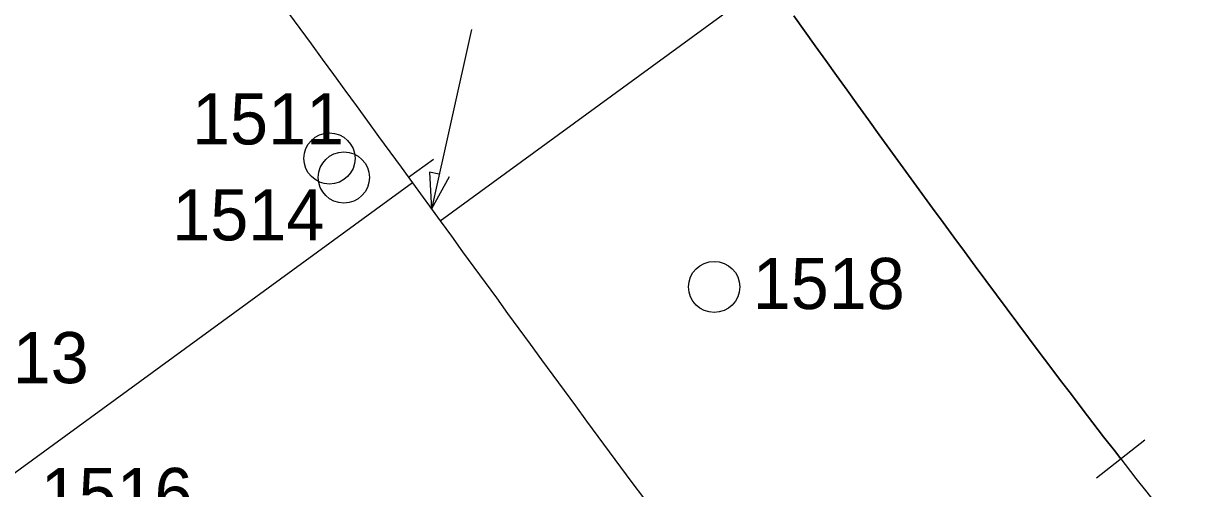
# Model space of a CAD drawing. Extents: x 7581380 to 7602708, y 543740 to 556109.
# Drawn here: x 7591832.4 to 7591946.3, y 549891.7 to 549937.2 of the extents above; entities that cross this region are included whole.
import ezdxf

# ---------------------------------------------------------------- set-up
doc = ezdxf.new("R2010")
doc.units = 0
for name, color, linetype in [('E_SURV_BNDRY_AccessControl', 7, 'Continuous'), ('E_SURV_BNDRY_ROW', 7, 'Continuous'), ('E_SURV_MON_FdMon', 7, 'Continuous'), ('E_SURV_MON_FdMonTx', 7, 'Continuous'), ('P_RW_ALIGN_Prim', 7, 'Continuous'), ('P_RW_ALIGN_PrimTic', 7, 'Continuous'), ('P_RW_ALIGN_PrimTx', 7, 'Continuous'), ('P_RW_FILE_AreaShapeFee', 7, 'Continuous'), ('P_RW_FILE_AreaShapeRemain', 7, 'Continuous')]:
    doc.layers.add(name, color=color, linetype=linetype)

msp = doc.modelspace()

# ---------------------------------------------------------------- linework, layer by layer
at = {"layer": 'E_SURV_BNDRY_AccessControl'}
msp.add_line((7591937.46, 549892.81), (7591942.19, 549896.5), dxfattribs=at)
msp.add_lwpolyline([(7591907.82, 549937.96), (7591908.87, 549936.5), (7591909.92, 549935.04), (7591910.96, 549933.58), (7591912.01, 549932.13), (7591913.05, 549930.68), (7591914.1, 549929.23), (7591915.14, 549927.78), (7591916.18, 549926.34), (7591917.23, 549924.9), (7591918.27, 549923.46), (7591919.31, 549922.03), (7591920.35, 549920.6), (7591921.4, 549919.17), (7591922.44, 549917.75), (7591923.48, 549916.33), (7591924.53, 549914.91), (7591925.57, 549913.5), (7591926.61, 549912.09), (7591927.66, 549910.68), (7591928.7, 549909.28), (7591929.75, 549907.88), (7591930.79, 549906.48), (7591931.84, 549905.09), (7591932.89, 549903.7), (7591933.94, 549902.32), (7591934.99, 549900.94), (7591936.04, 549899.56), (7591937.09, 549898.19), (7591938.14, 549896.82), (7591939.2, 549895.46), (7591939.82, 549894.65)], dxfattribs=at)
at = {"layer": 'E_SURV_BNDRY_ROW'}
msp.add_lwpolyline([(7591939.82, 549894.65), (7591940.25, 549894.1), (7591941.31, 549892.75), (7591942.37, 549891.4), (7591943.43, 549890.05), (7591944.49, 549888.71), (7591945.56, 549887.37), (7591946.62, 549886.04)], dxfattribs=at)
at = {"layer": 'E_SURV_MON_FdMon'}
for centre in [(7591862.4, 549924.02), (7591863.81, 549922.16), (7591900.04, 549911.46)]:
    msp.add_circle(centre, 2.5, dxfattribs=at)
at = {"layer": 'P_RW_ALIGN_Prim'}
msp.add_line((7591870.51, 549921.65), (7591873.23, 549917.92), dxfattribs=at)
msp.add_line((7591870.51, 549921.65), (7591873.23, 549917.92), dxfattribs=at)
for points in [[(7591858.39, 549938.23), (7591859.49, 549936.72), (7591860.6, 549935.22), (7591861.7, 549933.71), (7591862.8, 549932.21), (7591863.9, 549930.7), (7591865.01, 549929.19), (7591866.11, 549927.68), (7591867.21, 549926.18), (7591868.31, 549924.67), (7591869.41, 549923.16), (7591870.51, 549921.65)], [(7591873.23, 549917.92), (7591874.33, 549916.41), (7591875.43, 549914.9), (7591876.53, 549913.39), (7591877.63, 549911.88), (7591878.73, 549910.38), (7591879.83, 549908.87), (7591880.94, 549907.36), (7591882.04, 549905.85), (7591883.14, 549904.35), (7591884.25, 549902.84), (7591885.35, 549901.34), (7591886.46, 549899.84), (7591887.56, 549898.33), (7591888.67, 549896.83), (7591889.78, 549895.33), (7591890.89, 549893.83), (7591892, 549892.33), (7591893.12, 549890.83)]]:
    msp.add_lwpolyline(points, dxfattribs=at)
at = {"layer": 'P_RW_ALIGN_PrimTic'}
for points in [[(7591873.23, 549917.92), (7591994.43, 550006.3)], [(7591872.57, 549923.92), (7591870.14, 549922.15)], [(7591870.51, 549921.65), (7591749.31, 549833.27)]]:
    msp.add_lwpolyline(points, dxfattribs=at)
at = {"layer": 'P_RW_ALIGN_PrimTx'}
for p, q in [((7591876.31, 549936.63), (7591872.4, 549919.06)), ((7591873.15, 549922.48), (7591872.18, 549922.69)), ((7591872.18, 549922.69), (7591872.4, 549919.06)), ((7591872.4, 549919.06), (7591874.13, 549922.26))]:
    msp.add_line(p, q, dxfattribs=at)
at = {"layer": 'P_RW_FILE_AreaShapeFee'}
for points in [[(7591907.82, 549937.96), (7591908.87, 549936.5), (7591909.92, 549935.04), (7591910.96, 549933.58), (7591912.01, 549932.13), (7591913.05, 549930.68), (7591914.1, 549929.23), (7591915.14, 549927.78), (7591916.18, 549926.34), (7591917.23, 549924.9), (7591918.27, 549923.46), (7591919.31, 549922.03), (7591920.35, 549920.6), (7591921.4, 549919.17), (7591922.44, 549917.75), (7591923.48, 549916.33), (7591924.53, 549914.91), (7591925.57, 549913.5), (7591926.61, 549912.09), (7591927.66, 549910.68), (7591928.7, 549909.28), (7591929.75, 549907.88), (7591930.79, 549906.48), (7591931.84, 549905.09), (7591932.89, 549903.7), (7591933.94, 549902.32), (7591934.99, 549900.94), (7591936.04, 549899.56), (7591937.09, 549898.19), (7591938.14, 549896.82), (7591939.2, 549895.46), (7591939.82, 549894.65)], [(7591939.82, 549894.65), (7591939.2, 549895.46), (7591938.14, 549896.82), (7591937.09, 549898.19), (7591936.04, 549899.56), (7591934.99, 549900.94), (7591933.94, 549902.32), (7591932.89, 549903.7), (7591931.84, 549905.09), (7591930.79, 549906.48), (7591929.75, 549907.88), (7591928.7, 549909.28), (7591927.66, 549910.68), (7591926.61, 549912.09), (7591925.57, 549913.5), (7591924.53, 549914.91), (7591923.48, 549916.33), (7591922.44, 549917.75), (7591921.4, 549919.17), (7591920.35, 549920.6), (7591919.31, 549922.03), (7591918.27, 549923.46), (7591917.23, 549924.9), (7591916.18, 549926.34), (7591915.14, 549927.78), (7591914.1, 549929.23), (7591913.05, 549930.68), (7591912.01, 549932.13), (7591910.96, 549933.58), (7591909.92, 549935.04), (7591908.87, 549936.5), (7591907.82, 549937.96)], [(7591907.82, 549937.96), (7591908.87, 549936.5), (7591909.92, 549935.04), (7591910.96, 549933.58), (7591912.01, 549932.13), (7591913.05, 549930.68), (7591914.1, 549929.23), (7591915.14, 549927.78), (7591916.18, 549926.34), (7591917.23, 549924.9), (7591918.27, 549923.46), (7591919.31, 549922.03), (7591920.35, 549920.6), (7591921.4, 549919.17), (7591922.44, 549917.75), (7591923.48, 549916.33), (7591924.53, 549914.91), (7591925.57, 549913.5), (7591926.61, 549912.09), (7591927.66, 549910.68), (7591928.7, 549909.28), (7591929.75, 549907.88), (7591930.79, 549906.48), (7591931.84, 549905.09), (7591932.89, 549903.7), (7591933.94, 549902.32), (7591934.99, 549900.94), (7591936.04, 549899.56), (7591937.09, 549898.19), (7591938.14, 549896.82), (7591939.2, 549895.46), (7591939.82, 549894.65)], [(7591907.82, 549937.96), (7591908.87, 549936.5), (7591909.92, 549935.04), (7591910.96, 549933.58), (7591912.01, 549932.13), (7591913.05, 549930.68), (7591914.1, 549929.23), (7591915.14, 549927.78), (7591916.18, 549926.34), (7591917.23, 549924.9), (7591918.27, 549923.46), (7591919.31, 549922.03), (7591920.35, 549920.6), (7591921.4, 549919.17), (7591922.44, 549917.75), (7591923.48, 549916.33), (7591924.53, 549914.91), (7591925.57, 549913.5), (7591926.61, 549912.09), (7591927.66, 549910.68), (7591928.7, 549909.28), (7591929.75, 549907.88), (7591930.79, 549906.48), (7591931.84, 549905.09), (7591932.89, 549903.7), (7591933.94, 549902.32), (7591934.99, 549900.94), (7591936.04, 549899.56), (7591937.09, 549898.19), (7591938.14, 549896.82), (7591939.2, 549895.46), (7591939.82, 549894.65)], [(7591907.82, 549937.96), (7591908.87, 549936.5), (7591909.92, 549935.04), (7591910.96, 549933.58), (7591912.01, 549932.13), (7591913.05, 549930.68), (7591914.1, 549929.23), (7591915.14, 549927.78), (7591916.18, 549926.34), (7591917.23, 549924.9), (7591918.27, 549923.46), (7591919.31, 549922.03), (7591920.35, 549920.6), (7591921.4, 549919.17), (7591922.44, 549917.75), (7591923.48, 549916.33), (7591924.53, 549914.91), (7591925.57, 549913.5), (7591926.61, 549912.09), (7591927.66, 549910.68), (7591928.7, 549909.28), (7591929.75, 549907.88), (7591930.79, 549906.48), (7591931.84, 549905.09), (7591932.89, 549903.7), (7591933.94, 549902.32), (7591934.99, 549900.94), (7591936.04, 549899.56), (7591937.09, 549898.19), (7591938.14, 549896.82), (7591939.2, 549895.46), (7591939.82, 549894.65)], [(7591939.82, 549894.65), (7591939.2, 549895.46), (7591938.14, 549896.82), (7591937.09, 549898.19), (7591936.04, 549899.56), (7591934.99, 549900.94), (7591933.94, 549902.32), (7591932.89, 549903.7), (7591931.84, 549905.09), (7591930.79, 549906.48), (7591929.75, 549907.88), (7591928.7, 549909.28), (7591927.66, 549910.68), (7591926.61, 549912.09), (7591925.57, 549913.5), (7591924.53, 549914.91), (7591923.48, 549916.33), (7591922.44, 549917.75), (7591921.4, 549919.17), (7591920.35, 549920.6), (7591919.31, 549922.03), (7591918.27, 549923.46), (7591917.23, 549924.9), (7591916.18, 549926.34), (7591915.14, 549927.78), (7591914.1, 549929.23), (7591913.05, 549930.68), (7591912.01, 549932.13), (7591910.96, 549933.58), (7591909.92, 549935.04), (7591908.87, 549936.5), (7591907.82, 549937.96)], [(7591907.82, 549937.96), (7591908.87, 549936.5), (7591909.92, 549935.04), (7591910.96, 549933.58), (7591912.01, 549932.13), (7591913.05, 549930.68), (7591914.1, 549929.23), (7591915.14, 549927.78), (7591916.18, 549926.34), (7591917.23, 549924.9), (7591918.27, 549923.46), (7591919.31, 549922.03), (7591920.35, 549920.6), (7591921.4, 549919.17), (7591922.44, 549917.75), (7591923.48, 549916.33), (7591924.53, 549914.91), (7591925.57, 549913.5), (7591926.61, 549912.09), (7591927.66, 549910.68), (7591928.7, 549909.28), (7591929.75, 549907.88), (7591930.79, 549906.48), (7591931.84, 549905.09), (7591932.89, 549903.7), (7591933.94, 549902.32), (7591934.99, 549900.94), (7591936.04, 549899.56), (7591937.09, 549898.19), (7591938.14, 549896.82), (7591939.2, 549895.46), (7591939.82, 549894.65)], [(7591907.82, 549937.96), (7591908.87, 549936.5), (7591909.92, 549935.04), (7591910.96, 549933.58), (7591912.01, 549932.13), (7591913.05, 549930.68), (7591914.1, 549929.23), (7591915.14, 549927.78), (7591916.18, 549926.34), (7591917.23, 549924.9), (7591918.27, 549923.46), (7591919.31, 549922.03), (7591920.35, 549920.6), (7591921.4, 549919.17), (7591922.44, 549917.75), (7591923.48, 549916.33), (7591924.53, 549914.91), (7591925.57, 549913.5), (7591926.61, 549912.09), (7591927.66, 549910.68), (7591928.7, 549909.28), (7591929.75, 549907.88), (7591930.79, 549906.48), (7591931.84, 549905.09), (7591932.89, 549903.7), (7591933.94, 549902.32), (7591934.99, 549900.94), (7591936.04, 549899.56), (7591937.09, 549898.19), (7591938.14, 549896.82), (7591939.2, 549895.46), (7591939.82, 549894.65)]]:
    msp.add_lwpolyline(points, dxfattribs=at)
at = {"layer": 'P_RW_FILE_AreaShapeRemain'}
for points in [[(7591907.82, 549937.96), (7591908.87, 549936.5), (7591909.92, 549935.04), (7591910.96, 549933.58), (7591912.01, 549932.13), (7591913.05, 549930.68), (7591914.1, 549929.23), (7591915.14, 549927.78), (7591916.18, 549926.34), (7591917.23, 549924.9), (7591918.27, 549923.46), (7591919.31, 549922.03), (7591920.35, 549920.6), (7591921.4, 549919.17), (7591922.44, 549917.75), (7591923.48, 549916.33), (7591924.53, 549914.91), (7591925.57, 549913.5), (7591926.61, 549912.09), (7591927.66, 549910.68), (7591928.7, 549909.28), (7591929.75, 549907.88), (7591930.79, 549906.48), (7591931.84, 549905.09), (7591932.89, 549903.7), (7591933.94, 549902.32), (7591934.99, 549900.94), (7591936.04, 549899.56), (7591937.09, 549898.19), (7591938.14, 549896.82), (7591939.2, 549895.46), (7591939.82, 549894.65)], [(7591939.82, 549894.65), (7591940.25, 549894.1), (7591941.31, 549892.75), (7591942.37, 549891.4), (7591943.43, 549890.05), (7591944.49, 549888.71), (7591945.56, 549887.37), (7591946.62, 549886.04)]]:
    msp.add_lwpolyline(points, dxfattribs=at)

# ---------------------------------------------------------------- texts
at = {"layer": 'E_SURV_MON_FdMonTx'}
for s, p in [('1511', (7591848.95, 549925.39)), ('1514', (7591847.02, 549916.01)), ('1518', (7591903.81, 549909.3)), ('1513', (7591823.97, 549902.05)), ('1516', (7591834.14, 549888.77))]:
    msp.add_text(s, height=5, dxfattribs=at).set_placement(p)

doc.saveas('drawing.dxf')
